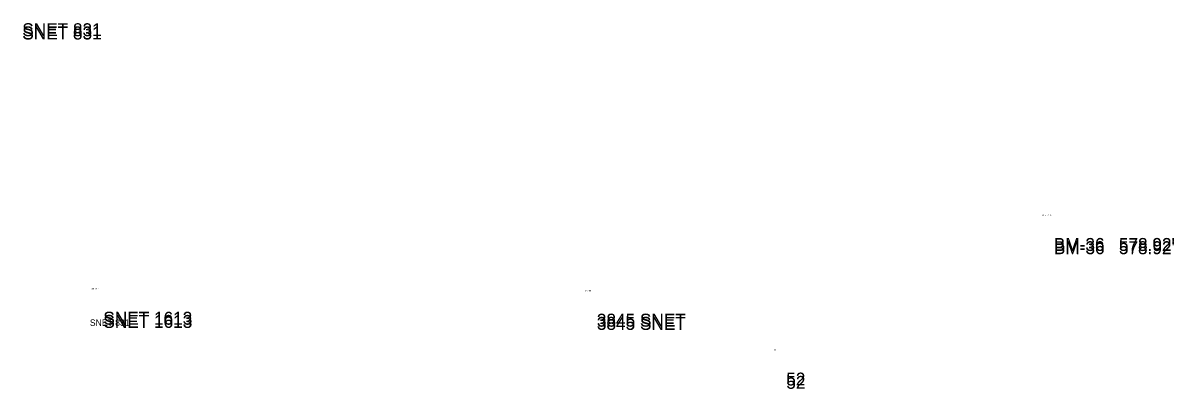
# Model space of a CAD drawing. Extents: x 5447 to 709667, y 4528 to 375472.
# Drawn here: x 708423.5 to 708709.7, y 374063.1 to 374154.1 of the extents above; entities that cross this region are included whole.
import ezdxf

# ---------------------------------------------------------------- set-up
doc = ezdxf.new("R2010")
doc.units = 0
doc.layers.add('SV_SURVEY_NOTES', color=7, linetype='Continuous')

msp = doc.modelspace()

# ---------------------------------------------------------------- texts
at = {"layer": 'SV_SURVEY_NOTES'}
for s, height, p in [('SNET 831', 3.2, (708423.35, 374150.83)), ('SNET 831', 3.2, (708423.35, 374150.83)), ('SNET 831', 3.2, (708423.35, 374150.83)), ('SNET 831', 3.2, (708423.35, 374150.03)), ('SNET 831', 3.2, (708423.35, 374149.99)), ('SNET 831', 3.2, (708423.36, 374150.82)), ('SNET 831', 3.2, (708423.36, 374150.82)), ('SNET 831', 3.2, (708423.36, 374150.82)), ('SNET 831', 3.2, (708423.36, 374150.82)), ('SNET 831', 3.2, (708423.36, 374150.82)), ('SNET 831', 3.2, (708423.36, 374150.02)), ("BM-36   578.92'", 0.25, (708676.9, 374106.22)), ("BM-36   578.92'", 3.2, (708679.86, 374097.46)), ("BM-36   578.92'", 3.2, (708679.86, 374097.46)), ("BM-36   578.92'", 3.2, (708679.86, 374097.46)), ("BM-36   578.92'", 3.2, (708679.86, 374096.66)), ("BM-36   578.92'", 3.2, (708679.87, 374097.43)), ("BM-36   578.92'", 3.2, (708679.87, 374097.43)), ("BM-36   578.92'", 3.2, (708679.87, 374097.43)), ("BM-36   578.92'", 3.2, (708679.87, 374097.43)), ("BM-36   578.92'", 3.2, (708679.87, 374097.43)), ("BM-36   578.92'", 3.2, (708679.87, 374096.63)), ("BM-36   578.92'", 3.2, (708679.87, 374096.63)), ('SNET 1613', 0.25, (708440.54, 374087.89)), ('3845 SNET', 0.25, (708563.26, 374087.41)), ('SNET 1613', 3.2, (708443.5, 374079.13)), ('SNET 1613', 3.2, (708443.5, 374079.13)), ('SNET 1613', 3.2, (708443.5, 374079.13)), ('SNET 1613', 3.2, (708443.5, 374078.33)), ('SNET 1613', 3.2, (708443.52, 374079.11)), ('SNET 1613', 3.2, (708443.52, 374079.11)), ('SNET 1613', 3.2, (708443.52, 374079.11)), ('SNET 1613', 3.2, (708443.52, 374079.11)), ('SNET 1613', 3.2, (708443.52, 374079.11)), ('SNET 1613', 3.2, (708443.52, 374078.31)), ('SNET 1613', 3.2, (708443.52, 374078.31)), ('3845 SNET', 3.2, (708566.22, 374078.65)), ('3845 SNET', 3.2, (708566.22, 374078.65)), ('3845 SNET', 3.2, (708566.22, 374078.65)), ('3845 SNET', 3.2, (708566.24, 374078.62)), ('3845 SNET', 3.2, (708566.24, 374078.62)), ('3845 SNET', 3.2, (708566.24, 374078.62)), ('3845 SNET', 3.2, (708566.24, 374078.62)), ('3845 SNET', 3.2, (708566.24, 374078.62)), ('SNET 831', 1.6, (708440.16, 374078.82)), ('3845 SNET', 3.2, (708566.22, 374077.85)), ('3845 SNET', 3.2, (708566.24, 374077.82)), ('3845 SNET', 3.2, (708566.24, 374077.82)), ('52', 0.25, (708610.35, 374072.77)), ('52', 0.25, (708610.35, 374072.77)), ('52', 0.25, (708610.35, 374072.77)), ('52', 0.25, (708610.35, 374072.77)), ('52', 0.25, (708610.35, 374072.77)), ('52', 0.25, (708610.35, 374072.77)), ('52', 0.25, (708610.35, 374072.77)), ('52', 0.25, (708610.35, 374072.77)), ('52', 0.25, (708610.35, 374072.77)), ('52', 0.25, (708610.35, 374072.77)), ('52', 0.25, (708610.35, 374072.77)), ('52', 0.25, (708610.35, 374072.77)), ('52', 0.25, (708610.38, 374072.71)), ('52', 3.2, (708613.31, 374064.01)), ('52', 3.2, (708613.31, 374064.01)), ('52', 3.2, (708613.31, 374064.01)), ('52', 3.2, (708613.31, 374064.01)), ('52', 3.2, (708613.31, 374064.01)), ('52', 3.2, (708613.31, 374064.01)), ('52', 3.2, (708613.31, 374064.01)), ('52', 3.2, (708613.31, 374064.01)), ('52', 3.2, (708613.31, 374064.01)), ('52', 3.2, (708613.31, 374064.01)), ('52', 3.2, (708613.31, 374064.01)), ('52', 3.2, (708613.31, 374064.01)), ('52', 3.2, (708613.31, 374064.01)), ('52', 3.2, (708613.31, 374064.01)), ('52', 3.2, (708613.31, 374064.01)), ('52', 3.2, (708613.31, 374064.01)), ('52', 3.2, (708613.31, 374064.01)), ('52', 3.2, (708613.31, 374064.01)), ('52', 3.2, (708613.31, 374064.01)), ('52', 3.2, (708613.31, 374064.01)), ('52', 3.2, (708613.31, 374064.01)), ('52', 3.2, (708613.31, 374064.01)), ('52', 3.2, (708613.31, 374064.01)), ('52', 3.2, (708613.31, 374064.01)), ('52', 3.2, (708613.31, 374064.01)), ('52', 3.2, (708613.31, 374064.01)), ('52', 3.2, (708613.31, 374064.01)), ('52', 3.2, (708613.31, 374064.01)), ('52', 3.2, (708613.31, 374064.01)), ('52', 3.2, (708613.31, 374064.01)), ('52', 3.2, (708613.31, 374064.01)), ('52', 3.2, (708613.31, 374064.01)), ('52', 3.2, (708613.31, 374064.01)), ('52', 3.2, (708613.31, 374064.01)), ('52', 3.2, (708613.31, 374064.01)), ('52', 3.2, (708613.31, 374064.01)), ('52', 3.2, (708613.31, 374064.01)), ('52', 3.2, (708613.31, 374064.01)), ('52', 3.2, (708613.31, 374064.01)), ('52', 3.2, (708613.33, 374063.98)), ('52', 3.2, (708613.33, 374063.98)), ('52', 3.2, (708613.33, 374063.98)), ('52', 3.2, (708613.33, 374063.98)), ('52', 3.2, (708613.33, 374063.98)), ('52', 3.2, (708613.33, 374063.98)), ('52', 3.2, (708613.33, 374063.98)), ('52', 3.2, (708613.33, 374063.98)), ('52', 3.2, (708613.33, 374063.98)), ('52', 3.2, (708613.33, 374063.98)), ('52', 3.2, (708613.33, 374063.98)), ('52', 3.2, (708613.33, 374063.98)), ('52', 3.2, (708613.33, 374063.98)), ('52', 3.2, (708613.33, 374063.98)), ('52', 3.2, (708613.33, 374063.98)), ('52', 3.2, (708613.33, 374063.98)), ('52', 3.2, (708613.33, 374063.98)), ('52', 3.2, (708613.33, 374063.98)), ('52', 3.2, (708613.33, 374063.98)), ('52', 3.2, (708613.33, 374063.98)), ('52', 3.2, (708613.33, 374063.98)), ('52', 3.2, (708613.33, 374063.98)), ('52', 3.2, (708613.33, 374063.98)), ('52', 3.2, (708613.33, 374063.98)), ('52', 3.2, (708613.33, 374063.98)), ('52', 3.2, (708613.33, 374063.98)), ('52', 3.2, (708613.33, 374063.98)), ('52', 3.2, (708613.33, 374063.98)), ('52', 3.2, (708613.33, 374063.98)), ('52', 3.2, (708613.33, 374063.98)), ('52', 3.2, (708613.33, 374063.98)), ('52', 3.2, (708613.33, 374063.98)), ('52', 3.2, (708613.33, 374063.98)), ('52', 3.2, (708613.33, 374063.98)), ('52', 3.2, (708613.33, 374063.98)), ('52', 3.2, (708613.33, 374063.98)), ('52', 3.2, (708613.33, 374063.98)), ('52', 3.2, (708613.33, 374063.98)), ('52', 3.2, (708613.33, 374063.98)), ('52', 3.2, (708613.33, 374063.98)), ('52', 3.2, (708613.33, 374063.98)), ('52', 3.2, (708613.33, 374063.98)), ('52', 3.2, (708613.33, 374063.98)), ('52', 3.2, (708613.33, 374063.98)), ('52', 3.2, (708613.33, 374063.98)), ('52', 3.2, (708613.33, 374063.98)), ('52', 3.2, (708613.33, 374063.98)), ('52', 3.2, (708613.33, 374063.98)), ('52', 3.2, (708613.33, 374063.98)), ('52', 3.2, (708613.33, 374063.98)), ('52', 3.2, (708613.33, 374063.98)), ('52', 3.2, (708613.33, 374063.98)), ('52', 3.2, (708613.33, 374063.98)), ('52', 3.2, (708613.33, 374063.98)), ('52', 3.2, (708613.33, 374063.98)), ('52', 3.2, (708613.33, 374063.98)), ('52', 3.2, (708613.33, 374063.98)), ('52', 3.2, (708613.33, 374063.98)), ('52', 3.2, (708613.33, 374063.98)), ('52', 3.2, (708613.33, 374063.98)), ('52', 3.2, (708613.33, 374063.98)), ('52', 3.2, (708613.33, 374063.98)), ('52', 3.2, (708613.33, 374063.98)), ('52', 3.2, (708613.33, 374063.98)), ('52', 3.2, (708613.33, 374063.98)), ('52', 3.2, (708613.33, 374063.98)), ('52', 3.2, (708613.33, 374063.98)), ('52', 3.2, (708613.33, 374063.98)), ('52', 3.2, (708613.31, 374063.21)), ('52', 3.2, (708613.31, 374063.21)), ('52', 3.2, (708613.31, 374063.21)), ('52', 3.2, (708613.31, 374063.21)), ('52', 3.2, (708613.31, 374063.21)), ('52', 3.2, (708613.31, 374063.21)), ('52', 3.2, (708613.31, 374063.21)), ('52', 3.2, (708613.31, 374063.21)), ('52', 3.2, (708613.31, 374063.21)), ('52', 3.2, (708613.31, 374063.21)), ('52', 3.2, (708613.31, 374063.21)), ('52', 3.2, (708613.31, 374063.21)), ('52', 3.2, (708613.33, 374063.18)), ('52', 3.2, (708613.33, 374063.18)), ('52', 3.2, (708613.33, 374063.18))]:
    msp.add_text(s, height=height, dxfattribs=at).set_placement(p)

doc.saveas('drawing.dxf')
